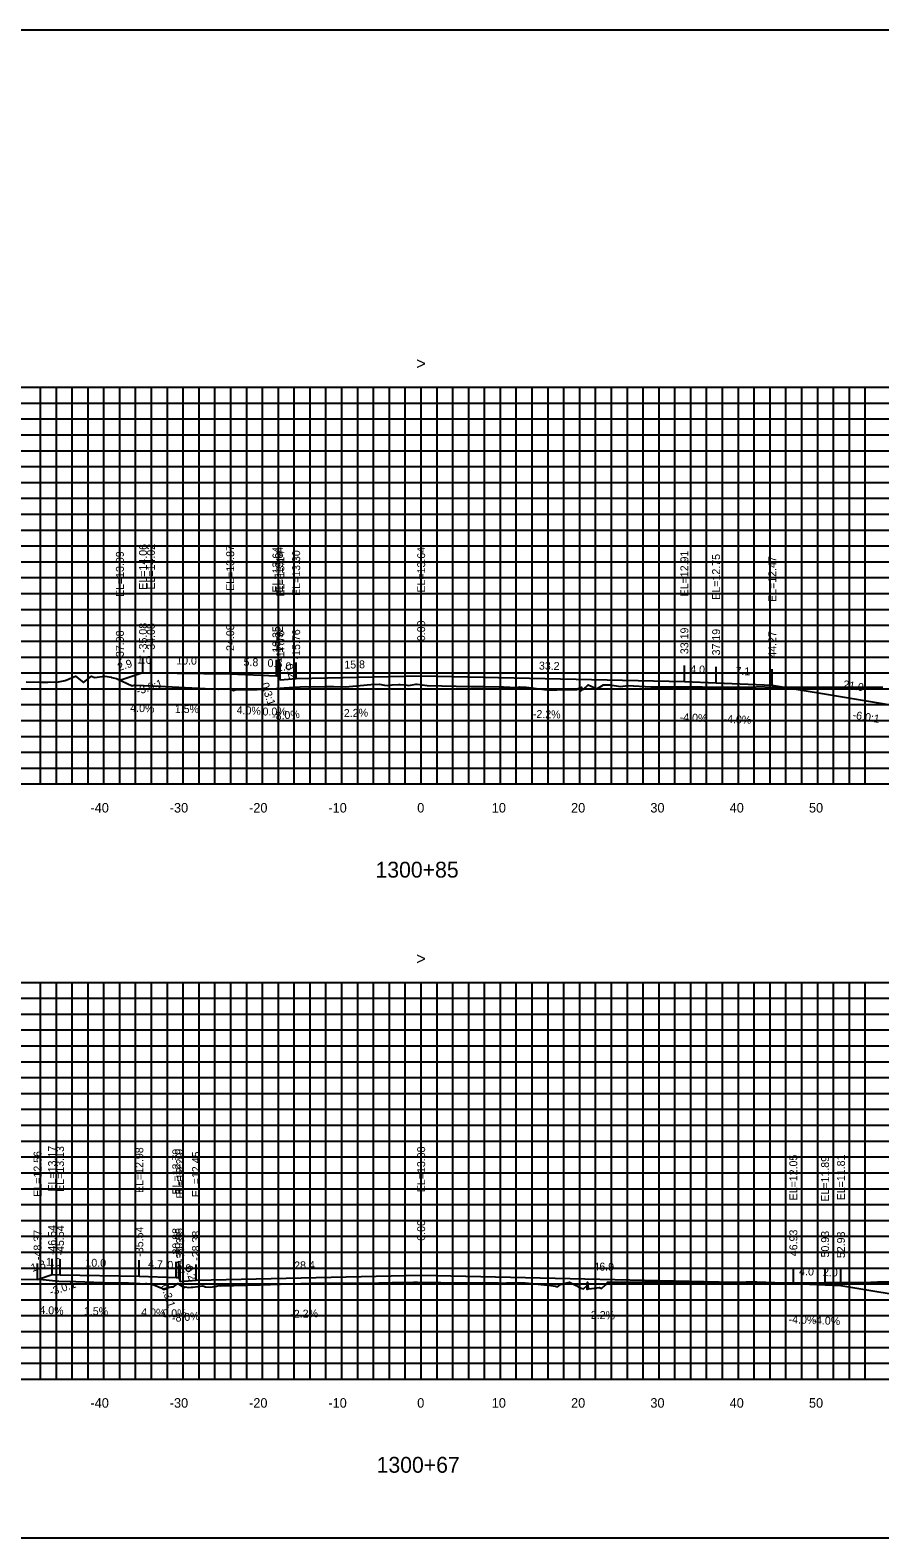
# Model space of a CAD drawing. Extents: x 1797714 to 1804825, y 249015 to 250269.
# Drawn here: x 1802214.9 to 1802322, y 249628.2 to 249818.2 of the extents above; entities that cross this region are included whole.
import ezdxf

# ---------------------------------------------------------------- set-up
doc = ezdxf.new("R2010")
doc.units = 0
for name, color, linetype in [('1', 7, 'Continuous'), ('10', 7, 'Continuous'), ('3', 7, 'Continuous'), ('4', 7, 'Continuous'), ('60', 7, 'Continuous'), ('CL-CNST', 7, 'Continuous'), ('Level 62', 7, 'Continuous'), ('M-ROADS', 7, 'Continuous')]:
    doc.layers.add(name, color=color, linetype=linetype)

msp = doc.modelspace()

# ---------------------------------------------------------------- linework, layer by layer
for p, q in [((1802226.17, 249736.26), (1802226.17, 249738.26)), ((1802229.08, 249737.23), (1802229.08, 249739.23)), ((1802230.08, 249737.19), (1802230.08, 249739.19)), ((1802240.08, 249737.04), (1802240.08, 249739.04)), ((1802245.91, 249736.8), (1802245.91, 249738.8)), ((1802246.24, 249736.8), (1802246.24, 249738.8)), ((1802246.4, 249736.3), (1802246.4, 249738.3)), ((1802248.4, 249736.46), (1802248.4, 249738.46)), ((1802264.16, 249736.81), (1802264.16, 249738.81)), ((1802297.35, 249736.08), (1802297.35, 249738.08)), ((1802301.35, 249735.92), (1802301.35, 249737.92)), ((1802308.43, 249735.64), (1802308.43, 249737.64)), ((1802215.79, 249660.73), (1802215.79, 249662.73)), ((1802217.62, 249661.34), (1802217.62, 249663.34)), ((1802218.62, 249661.3), (1802218.62, 249663.3)), ((1802228.62, 249661.15), (1802228.62, 249663.15)), ((1802233.28, 249660.96), (1802233.28, 249662.96)), ((1802233.61, 249660.96), (1802233.61, 249662.96)), ((1802233.77, 249660.46), (1802233.77, 249662.46)), ((1802235.77, 249660.62), (1802235.77, 249662.62)), ((1802264.16, 249661.25), (1802264.16, 249663.25)), ((1802311.09, 249660.21), (1802311.09, 249662.21)), ((1802315.09, 249660.05), (1802315.09, 249662.05)), ((1802317.09, 249659.97), (1802317.09, 249661.97))]:
    msp.add_line(p, q)
msp.add_lwpolyline([(1802114.16, 249628.17), (1802414.16, 249628.17), (1802414.16, 249818.17), (1802114.16, 249818.17)], close=True)
at = {"layer": '60'}
for p, q in [((1802114.16, 249723.17), (1802414.16, 249723.17)), ((1802224.16, 249723.11), (1802224.16, 249723.17)), ((1802234.16, 249723.11), (1802234.16, 249723.17)), ((1802244.16, 249723.11), (1802244.16, 249723.17)), ((1802254.16, 249723.11), (1802254.16, 249723.17)), ((1802264.16, 249723.11), (1802264.16, 249723.17)), ((1802274.16, 249723.11), (1802274.16, 249723.17)), ((1802284.16, 249723.11), (1802284.16, 249723.17)), ((1802294.16, 249723.11), (1802294.16, 249723.17)), ((1802304.16, 249723.11), (1802304.16, 249723.17)), ((1802314.16, 249723.11), (1802314.16, 249723.17)), ((1802114.16, 249648.17), (1802414.16, 249648.17)), ((1802224.16, 249648.11), (1802224.16, 249648.17)), ((1802234.16, 249648.11), (1802234.16, 249648.17)), ((1802244.16, 249648.11), (1802244.16, 249648.17)), ((1802254.16, 249648.11), (1802254.16, 249648.17)), ((1802264.16, 249648.11), (1802264.16, 249648.17)), ((1802274.16, 249648.11), (1802274.16, 249648.17)), ((1802284.16, 249648.11), (1802284.16, 249648.17)), ((1802294.16, 249648.11), (1802294.16, 249648.17)), ((1802304.16, 249648.11), (1802304.16, 249648.17)), ((1802314.16, 249648.11), (1802314.16, 249648.17))]:
    msp.add_line(p, q, dxfattribs=at)
at = {"layer": 'CL-CNST'}
for points in [[(1802226.17, 249736.26), (1802229.08, 249737.23), (1802230.08, 249737.19), (1802240.08, 249737.04), (1802245.91, 249736.8), (1802246.24, 249736.8), (1802246.4, 249736.3), (1802248.4, 249736.46), (1802264.16, 249736.81), (1802297.35, 249736.08), (1802301.35, 249735.92), (1802308.43, 249735.64), (1802329.43, 249732.14), (1802333.43, 249732.14), (1802345.04, 249735.04)], [(1802215.79, 249660.73), (1802217.62, 249661.34), (1802218.62, 249661.3), (1802228.62, 249661.15), (1802233.28, 249660.96), (1802233.61, 249660.96), (1802233.77, 249660.46), (1802235.77, 249660.62), (1802264.16, 249661.25), (1802311.09, 249660.21), (1802315.09, 249660.05), (1802317.09, 249659.97), (1802338.09, 249656.47), (1802342.09, 249656.47), (1802355.26, 249659.77)]]:
    msp.add_lwpolyline(points, dxfattribs=at)
at = {"layer": 'Level 62'}
for p, q in [((1802114.16, 249773.17), (1802414.16, 249773.17)), ((1802216.16, 249723.17), (1802216.16, 249773.17)), ((1802218.16, 249723.17), (1802218.16, 249773.17)), ((1802220.16, 249723.17), (1802220.16, 249773.17)), ((1802222.16, 249723.17), (1802222.16, 249773.17)), ((1802224.16, 249723.17), (1802224.16, 249773.17)), ((1802226.16, 249723.17), (1802226.16, 249773.17)), ((1802228.16, 249723.17), (1802228.16, 249773.17)), ((1802230.16, 249723.17), (1802230.16, 249773.17)), ((1802232.16, 249723.17), (1802232.16, 249773.17)), ((1802234.16, 249723.17), (1802234.16, 249773.17)), ((1802236.16, 249723.17), (1802236.16, 249773.17)), ((1802238.16, 249723.17), (1802238.16, 249773.17)), ((1802240.16, 249723.17), (1802240.16, 249773.17)), ((1802242.16, 249723.17), (1802242.16, 249773.17)), ((1802244.16, 249723.17), (1802244.16, 249773.17)), ((1802246.16, 249723.17), (1802246.16, 249773.17)), ((1802248.16, 249723.17), (1802248.16, 249773.17)), ((1802250.16, 249723.17), (1802250.16, 249773.17)), ((1802252.16, 249723.17), (1802252.16, 249773.17)), ((1802254.16, 249723.17), (1802254.16, 249773.17)), ((1802256.16, 249723.17), (1802256.16, 249773.17)), ((1802258.16, 249723.17), (1802258.16, 249773.17)), ((1802260.16, 249723.17), (1802260.16, 249773.17)), ((1802262.16, 249723.17), (1802262.16, 249773.17)), ((1802264.16, 249723.17), (1802264.16, 249773.17)), ((1802266.16, 249723.17), (1802266.16, 249773.17)), ((1802268.16, 249723.17), (1802268.16, 249773.17)), ((1802270.16, 249723.17), (1802270.16, 249773.17)), ((1802272.16, 249723.17), (1802272.16, 249773.17)), ((1802274.16, 249723.17), (1802274.16, 249773.17)), ((1802276.16, 249723.17), (1802276.16, 249773.17)), ((1802278.16, 249723.17), (1802278.16, 249773.17)), ((1802280.16, 249723.17), (1802280.16, 249773.17)), ((1802282.16, 249723.17), (1802282.16, 249773.17)), ((1802284.16, 249723.17), (1802284.16, 249773.17)), ((1802286.16, 249723.17), (1802286.16, 249773.17)), ((1802288.16, 249723.17), (1802288.16, 249773.17)), ((1802290.16, 249723.17), (1802290.16, 249773.17)), ((1802292.16, 249723.17), (1802292.16, 249773.17)), ((1802294.16, 249723.17), (1802294.16, 249773.17)), ((1802296.16, 249723.17), (1802296.16, 249773.17)), ((1802298.16, 249723.17), (1802298.16, 249773.17)), ((1802300.16, 249723.17), (1802300.16, 249773.17)), ((1802302.16, 249723.17), (1802302.16, 249773.17)), ((1802304.16, 249723.17), (1802304.16, 249773.17)), ((1802306.16, 249723.17), (1802306.16, 249773.17)), ((1802308.16, 249723.17), (1802308.16, 249773.17)), ((1802310.16, 249723.17), (1802310.16, 249773.17)), ((1802312.16, 249723.17), (1802312.16, 249773.17)), ((1802314.16, 249723.17), (1802314.16, 249773.17)), ((1802316.16, 249723.17), (1802316.16, 249773.17)), ((1802318.16, 249723.17), (1802318.16, 249773.17)), ((1802320.16, 249723.17), (1802320.16, 249773.17)), ((1802114.16, 249771.17), (1802414.16, 249771.17)), ((1802114.16, 249769.17), (1802414.16, 249769.17)), ((1802114.16, 249767.17), (1802414.16, 249767.17)), ((1802114.16, 249765.17), (1802414.16, 249765.17)), ((1802114.16, 249763.17), (1802414.16, 249763.17)), ((1802114.16, 249761.17), (1802414.16, 249761.17)), ((1802114.16, 249759.17), (1802414.16, 249759.17)), ((1802114.16, 249757.17), (1802414.16, 249757.17)), ((1802114.16, 249755.17), (1802414.16, 249755.17)), ((1802114.16, 249753.17), (1802414.16, 249753.17)), ((1802114.16, 249751.17), (1802414.16, 249751.17)), ((1802114.16, 249749.17), (1802414.16, 249749.17)), ((1802114.16, 249747.17), (1802414.16, 249747.17)), ((1802114.16, 249745.17), (1802414.16, 249745.17)), ((1802114.16, 249743.17), (1802414.16, 249743.17)), ((1802114.16, 249741.17), (1802414.16, 249741.17)), ((1802114.16, 249739.17), (1802414.16, 249739.17)), ((1802114.16, 249737.17), (1802414.16, 249737.17)), ((1802114.16, 249735.17), (1802414.16, 249735.17)), ((1802114.16, 249733.17), (1802414.16, 249733.17)), ((1802114.16, 249731.17), (1802414.16, 249731.17)), ((1802114.16, 249729.17), (1802414.16, 249729.17)), ((1802114.16, 249727.17), (1802414.16, 249727.17)), ((1802114.16, 249725.17), (1802414.16, 249725.17)), ((1802114.16, 249723.17), (1802414.16, 249723.17)), ((1802114.16, 249698.17), (1802414.16, 249698.17)), ((1802216.16, 249648.17), (1802216.16, 249698.17)), ((1802218.16, 249648.17), (1802218.16, 249698.17)), ((1802220.16, 249648.17), (1802220.16, 249698.17)), ((1802222.16, 249648.17), (1802222.16, 249698.17)), ((1802224.16, 249648.17), (1802224.16, 249698.17)), ((1802226.16, 249648.17), (1802226.16, 249698.17)), ((1802228.16, 249648.17), (1802228.16, 249698.17)), ((1802230.16, 249648.17), (1802230.16, 249698.17)), ((1802232.16, 249648.17), (1802232.16, 249698.17)), ((1802234.16, 249648.17), (1802234.16, 249698.17)), ((1802236.16, 249648.17), (1802236.16, 249698.17)), ((1802238.16, 249648.17), (1802238.16, 249698.17)), ((1802240.16, 249648.17), (1802240.16, 249698.17)), ((1802242.16, 249648.17), (1802242.16, 249698.17)), ((1802244.16, 249648.17), (1802244.16, 249698.17)), ((1802246.16, 249648.17), (1802246.16, 249698.17)), ((1802248.16, 249648.17), (1802248.16, 249698.17)), ((1802250.16, 249648.17), (1802250.16, 249698.17)), ((1802252.16, 249648.17), (1802252.16, 249698.17)), ((1802254.16, 249648.17), (1802254.16, 249698.17)), ((1802256.16, 249648.17), (1802256.16, 249698.17)), ((1802258.16, 249648.17), (1802258.16, 249698.17)), ((1802260.16, 249648.17), (1802260.16, 249698.17)), ((1802262.16, 249648.17), (1802262.16, 249698.17)), ((1802264.16, 249648.17), (1802264.16, 249698.17)), ((1802266.16, 249648.17), (1802266.16, 249698.17)), ((1802268.16, 249648.17), (1802268.16, 249698.17)), ((1802270.16, 249648.17), (1802270.16, 249698.17)), ((1802272.16, 249648.17), (1802272.16, 249698.17)), ((1802274.16, 249648.17), (1802274.16, 249698.17)), ((1802276.16, 249648.17), (1802276.16, 249698.17)), ((1802278.16, 249648.17), (1802278.16, 249698.17)), ((1802280.16, 249648.17), (1802280.16, 249698.17)), ((1802282.16, 249648.17), (1802282.16, 249698.17)), ((1802284.16, 249648.17), (1802284.16, 249698.17)), ((1802286.16, 249648.17), (1802286.16, 249698.17)), ((1802288.16, 249648.17), (1802288.16, 249698.17)), ((1802290.16, 249648.17), (1802290.16, 249698.17)), ((1802292.16, 249648.17), (1802292.16, 249698.17)), ((1802294.16, 249648.17), (1802294.16, 249698.17)), ((1802296.16, 249648.17), (1802296.16, 249698.17)), ((1802298.16, 249648.17), (1802298.16, 249698.17)), ((1802300.16, 249648.17), (1802300.16, 249698.17)), ((1802302.16, 249648.17), (1802302.16, 249698.17)), ((1802304.16, 249648.17), (1802304.16, 249698.17)), ((1802306.16, 249648.17), (1802306.16, 249698.17)), ((1802308.16, 249648.17), (1802308.16, 249698.17)), ((1802310.16, 249648.17), (1802310.16, 249698.17)), ((1802312.16, 249648.17), (1802312.16, 249698.17)), ((1802314.16, 249648.17), (1802314.16, 249698.17)), ((1802316.16, 249648.17), (1802316.16, 249698.17)), ((1802318.16, 249648.17), (1802318.16, 249698.17)), ((1802320.16, 249648.17), (1802320.16, 249698.17)), ((1802114.16, 249696.17), (1802414.16, 249696.17)), ((1802114.16, 249694.17), (1802414.16, 249694.17)), ((1802114.16, 249692.17), (1802414.16, 249692.17)), ((1802114.16, 249690.17), (1802414.16, 249690.17)), ((1802114.16, 249688.17), (1802414.16, 249688.17)), ((1802114.16, 249686.17), (1802414.16, 249686.17)), ((1802114.16, 249684.17), (1802414.16, 249684.17)), ((1802114.16, 249682.17), (1802414.16, 249682.17)), ((1802114.16, 249680.17), (1802414.16, 249680.17)), ((1802114.16, 249678.17), (1802414.16, 249678.17)), ((1802114.16, 249676.17), (1802414.16, 249676.17)), ((1802114.16, 249674.17), (1802414.16, 249674.17)), ((1802114.16, 249672.17), (1802414.16, 249672.17)), ((1802114.16, 249670.17), (1802414.16, 249670.17)), ((1802114.16, 249668.17), (1802414.16, 249668.17)), ((1802114.16, 249666.17), (1802414.16, 249666.17)), ((1802114.16, 249664.17), (1802414.16, 249664.17)), ((1802114.16, 249662.17), (1802414.16, 249662.17)), ((1802114.16, 249660.17), (1802414.16, 249660.17)), ((1802114.16, 249658.17), (1802414.16, 249658.17)), ((1802114.16, 249656.17), (1802414.16, 249656.17)), ((1802114.16, 249654.17), (1802414.16, 249654.17)), ((1802114.16, 249652.17), (1802414.16, 249652.17)), ((1802114.16, 249650.17), (1802414.16, 249650.17)), ((1802114.16, 249648.17), (1802414.16, 249648.17))]:
    msp.add_line(p, q, dxfattribs=at)
at = {"layer": 'M-ROADS'}
for points in [[(1802214.35, 249736.06), (1802216.33, 249736.01), (1802216.52, 249736.01), (1802217.1, 249736), (1802218.41, 249736.03), (1802219.29, 249736.23), (1802220.59, 249736.76), (1802221.59, 249735.97), (1802222.59, 249736.76), (1802222.96, 249736.57), (1802224.29, 249736.76), (1802225.1, 249736.65), (1802225.12, 249736.59), (1802225.75, 249736.46), (1802227.73, 249735.54), (1802227.8, 249735.59), (1802227.97, 249735.62), (1802227.98, 249735.63), (1802227.99, 249735.62), (1802228.04, 249735.62), (1802230.25, 249735.54), (1802230.26, 249735.54), (1802230.26, 249735.54), (1802230.27, 249735.54), (1802230.28, 249735.54), (1802238.57, 249735.12), (1802238.59, 249735.12), (1802239.88, 249735.22), (1802240.18, 249735.18), (1802240.48, 249734.94), (1802240.57, 249734.98), (1802240.95, 249735.08), (1802241.02, 249735.09), (1802241.19, 249735.09), (1802241.84, 249735.07), (1802242.64, 249735.06), (1802243.46, 249735.07), (1802243.98, 249735.11), (1802244.39, 249735.08), (1802246.89, 249735.27), (1802247.53, 249735.33), (1802249.62, 249735.44), (1802250.01, 249735.43), (1802250.65, 249735.44), (1802252.08, 249735.43), (1802252.22, 249735.46), (1802253.15, 249735.47), (1802254.6, 249735.43), (1802256.47, 249735.59), (1802257.8, 249735.71), (1802258.91, 249735.73), (1802259.54, 249735.64), (1802259.94, 249735.58), (1802260.51, 249735.68), (1802261.31, 249735.72), (1802261.51, 249735.71), (1802262.16, 249735.67), (1802262.62, 249735.6), (1802263.48, 249735.75), (1802263.53, 249735.76), (1802263.55, 249735.76), (1802263.66, 249735.75), (1802264.91, 249735.56), (1802270.43, 249735.46), (1802271.62, 249735.44), (1802272.04, 249735.44), (1802274.01, 249735.43), (1802274.33, 249735.42), (1802274.36, 249735.41), (1802274.45, 249735.41), (1802274.54, 249735.41), (1802276.12, 249735.32), (1802276.59, 249735.41), (1802277.4, 249735.37), (1802280.05, 249735.05), (1802281.25, 249735.03), (1802283.07, 249735.08), (1802283.63, 249735.09), (1802283.82, 249735.06), (1802283.87, 249735.17), (1802284.03, 249735.23), (1802284.13, 249735.12), (1802284.26, 249734.92), (1802284.32, 249734.93), (1802284.33, 249734.93), (1802284.34, 249734.96), (1802284.37, 249735.39), (1802284.42, 249735.04), (1802284.57, 249735.08), (1802284.87, 249735.32), (1802285.22, 249735.66), (1802285.96, 249735.32), (1802286.3, 249735.17), (1802286.32, 249735.17), (1802287.14, 249735.68), (1802288, 249735.68), (1802289.29, 249735.44), (1802290.23, 249735.56), (1802293.11, 249735.41), (1802293.58, 249735.41), (1802293.71, 249735.41), (1802294.35, 249735.41), (1802299.6, 249735.42), (1802304.56, 249735.38), (1802305.24, 249735.38), (1802305.31, 249735.38), (1802305.35, 249735.38), (1802305.67, 249735.38), (1802307.14, 249735.44), (1802307.77, 249735.38), (1802308.22, 249735.38), (1802309.74, 249735.38), (1802311.11, 249735.38), (1802321.47, 249735.35), (1802322.38, 249735.35)], [(1802212.33, 249660.77), (1802216.44, 249660.72), (1802218.49, 249660.53), (1802220.61, 249660.46), (1802224.04, 249660.33), (1802227.27, 249660.29), (1802228.67, 249660.24), (1802229.39, 249660.19), (1802229.45, 249660.2), (1802229.58, 249660.2), (1802230.22, 249660.15), (1802231.67, 249659.56), (1802232.62, 249659.78), (1802232.95, 249659.81), (1802233.49, 249660.2), (1802234.15, 249659.82), (1802234.31, 249659.72), (1802234.31, 249659.76), (1802234.34, 249659.8), (1802234.81, 249659.71), (1802235.16, 249659.75), (1802235.36, 249659.76), (1802236.63, 249659.93), (1802236.97, 249659.81), (1802237.61, 249659.75), (1802238.37, 249659.9), (1802238.65, 249659.96), (1802238.69, 249659.96), (1802238.85, 249659.92), (1802242.27, 249660.02), (1802243.87, 249660.06), (1802250.31, 249660.27), (1802250.47, 249660.26), (1802252.72, 249660.26), (1802253.02, 249660.27), (1802253.22, 249660.27), (1802255.29, 249660.25), (1802256.57, 249660.27), (1802256.69, 249660.27), (1802257.13, 249660.28), (1802260.52, 249660.34), (1802261.2, 249660.33), (1802262.89, 249660.33), (1802263.17, 249660.36), (1802263.25, 249660.37), (1802263.71, 249660.37), (1802265.5, 249660.34), (1802266.66, 249660.35), (1802270.51, 249660.31), (1802272.29, 249660.3), (1802272.92, 249660.29), (1802273.9, 249660.32), (1802274.66, 249660.28), (1802274.94, 249660.3), (1802275, 249660.31), (1802275.42, 249660.31), (1802277.26, 249660.3), (1802280.53, 249659.96), (1802281.1, 249659.9), (1802281.34, 249659.81), (1802281.74, 249660.09), (1802282.86, 249660.39), (1802283.69, 249659.97), (1802283.83, 249659.91), (1802283.88, 249659.9), (1802284.29, 249659.65), (1802284.33, 249659.63), (1802284.33, 249659.63), (1802284.34, 249659.63), (1802284.35, 249659.62), (1802284.65, 249659.56), (1802284.67, 249659.61), (1802285.03, 249659.93), (1802285.08, 249659.45), (1802285.08, 249660.08), (1802285.1, 249660.21), (1802285.15, 249660.38), (1802285.21, 249659.64), (1802285.24, 249659.54), (1802285.24, 249659.53), (1802285.3, 249659.53), (1802286.64, 249659.7), (1802286.91, 249659.61), (1802287.42, 249660.06), (1802287.65, 249660.39), (1802288.57, 249660.39), (1802289.02, 249660.4), (1802289.05, 249660.37), (1802289.07, 249660.39), (1802289.08, 249660.4), (1802289.08, 249660.4), (1802289.1, 249660.34), (1802289.24, 249660.4), (1802289.74, 249660.4), (1802292.24, 249660.39), (1802301.46, 249660.43), (1802302.02, 249660.35), (1802303.61, 249660.38), (1802305.15, 249660.42), (1802305.93, 249660.43), (1802306.49, 249660.44), (1802308.74, 249660.36), (1802309.29, 249660.3), (1802309.3, 249660.31), (1802309.39, 249660.31), (1802309.77, 249660.3), (1802315.05, 249660.35), (1802320.02, 249660.35), (1802321.69, 249660.45), (1802323.18, 249660.45)]]:
    msp.add_lwpolyline(points, dxfattribs=at)

# ---------------------------------------------------------------- texts
for s, rotation, p in [('-3.0:1', 18.4349, (1802228.42, 249734.37)), ('0.3:1', 288.4353, (1802243.95, 249735.76)), ('-6.0:1', 350.5377, (1802318.51, 249731.42)), ('-3.0:1', 18.4349, (1802217.49, 249658.66)), ('0.3:1', 288.4353, (1802231.32, 249659.92))]:
    msp.add_text(s, height=1, rotation=rotation).set_placement(p)
at = {"layer": '1'}
for s, p in [('1300+85', (1802258.4, 249711.37)), ('1300+67', (1802258.54, 249636.37))]:
    msp.add_text(s, height=2, dxfattribs=at).set_placement(p)
at = {"layer": '10'}
for s, p in [('-40', (1802222.46, 249719.57)), ('-30', (1802232.46, 249719.57)), ('-20', (1802242.46, 249719.57)), ('-10', (1802252.46, 249719.57)), ('0', (1802263.66, 249719.57)), ('10', (1802273.06, 249719.57)), ('20', (1802283.06, 249719.57)), ('30', (1802293.06, 249719.57)), ('40', (1802303.06, 249719.57)), ('50', (1802313.06, 249719.57)), ('-40', (1802222.46, 249644.57)), ('-30', (1802232.46, 249644.57)), ('-20', (1802242.46, 249644.57)), ('-10', (1802252.46, 249644.57)), ('0', (1802263.66, 249644.57)), ('10', (1802273.06, 249644.57)), ('20', (1802283.06, 249644.57)), ('30', (1802293.06, 249644.57)), ('40', (1802303.06, 249644.57)), ('50', (1802313.06, 249644.57))]:
    msp.add_text(s, height=1.2, dxfattribs=at).set_placement(p)
at = {"layer": '3'}
for s, p in [('EL=14.06', (1802229.58, 249747.65)), ('EL=14.02', (1802230.58, 249747.66)), ('EL=13.87', (1802240.58, 249747.51)), ('EL=13.09', (1802226.67, 249746.73)), ('EL=13.64', (1802246.41, 249747.28)), ('EL=13.64', (1802246.74, 249747.28)), ('EL=13.14', (1802246.9, 249746.78)), ('EL=13.30', (1802248.9, 249746.86)), ('EL=13.64', (1802264.66, 249747.28)), ('EL=12.91', (1802297.85, 249746.81)), ('EL=12.75', (1802301.85, 249746.39)), ('EL=12.47', (1802308.93, 249746.11)), ('0.00', (1802264.66, 249741.17)), ('-37.98', (1802226.67, 249738.72)), ('-35.08', (1802229.58, 249739.68)), ('-34.08', (1802230.58, 249739.64)), ('-24.08', (1802240.58, 249739.49)), ('-18.25', (1802246.41, 249739.26)), ('-17.92', (1802246.74, 249739.26)), ('-17.76', (1802246.9, 249738.71)), ('-15.76', (1802248.9, 249738.87)), ('33.19', (1802297.85, 249739.53)), ('37.19', (1802301.85, 249739.37)), ('44.27', (1802308.93, 249739.09)), ('EL=13.17', (1802218.12, 249671.81)), ('EL=13.13', (1802219.12, 249671.77)), ('EL=12.98', (1802229.12, 249671.62)), ('EL=12.79', (1802233.78, 249671.43)), ('EL=12.79', (1802234.11, 249671.43)), ('EL=13.08', (1802264.66, 249671.72)), ('EL=12.56', (1802216.29, 249671.15)), ('EL=12.29', (1802234.27, 249670.93)), ('EL=12.45', (1802236.27, 249671.09)), ('EL=12.05', (1802311.59, 249670.69)), ('EL=11.89', (1802315.59, 249670.53)), ('EL=11.81', (1802317.59, 249670.7)), ('0.00', (1802264.66, 249665.61)), ('-48.37', (1802216.29, 249663.18)), ('-46.54', (1802218.12, 249663.79)), ('-45.54', (1802219.12, 249663.75)), ('-35.54', (1802229.12, 249663.6)), ('-30.88', (1802233.78, 249663.42)), ('-30.55', (1802234.11, 249663.42)), ('-30.38', (1802234.27, 249662.92)), ('-28.38', (1802236.27, 249663.08)), ('46.93', (1802311.59, 249663.66)), ('50.93', (1802315.59, 249663.5)), ('52.93', (1802317.59, 249663.42))]:
    msp.add_text(s, height=1, rotation=90, dxfattribs=at).set_placement(p)
at = {"layer": '4'}
for s, rotation, p in [('2.9', 18.4349, (1802226.06, 249737.38)), ('1.0', 357.7094, (1802228.3, 249738.36)), ('10.0', 359.1406, (1802233.27, 249738.24)), ('5.8', 357.7094, (1802241.75, 249738.07)), ('2.0', 4.5739, (1802246, 249737.38)), ('0.2', 288.4353, (1802246.96, 249738.12)), ('15.8', 1.2603, (1802254.48, 249737.7)), ('33.2', 358.7397, (1802279, 249737.59)), ('4.0', 357.7094, (1802298.07, 249737.15)), ('7.1', 357.7094, (1802303.78, 249736.93)), ('21.0', 350.5377, (1802317.31, 249735.27)), ('4.0%', 357.7094, (1802227.46, 249732.29)), ('1.5%', 359.1406, (1802233.09, 249732.14)), ('4.0%', 357.7094, (1802240.88, 249732)), ('-8.0%', 4.5739, (1802245.4, 249731.21)), ('-2.2%', 1.2603, (1802253.98, 249731.59)), ('-2.2%', 358.7397, (1802278.24, 249731.5)), ('-4.0%', 357.7094, (1802296.74, 249731.1)), ('-4.0%', 357.7094, (1802302.28, 249730.88)), ('1.8', 18.4349, (1802215.14, 249661.67)), ('1.0', 357.7094, (1802216.84, 249662.47)), ('10.0', 359.1406, (1802221.82, 249662.35)), ('4.7', 357.7094, (1802229.71, 249662.2)), ('2.0', 4.5739, (1802233.37, 249661.53)), ('0.2', 288.4353, (1802234.33, 249662.28)), ('28.4', 1.2603, (1802248.16, 249661.99)), ('46.9', 358.7397, (1802285.87, 249661.87)), ('4.0', 357.7094, (1802311.81, 249661.29)), ('2.0', 357.7094, (1802314.81, 249661.17)), ('4.0%', 357.7094, (1802216.01, 249656.4)), ('1.5%', 359.1406, (1802221.63, 249656.25)), ('4.0%', 357.7094, (1802228.84, 249656.13)), ('-8.0%', 4.5739, (1802232.77, 249655.36)), ('-2.2%', 1.2603, (1802247.67, 249655.88)), ('-2.2%', 358.7397, (1802285.1, 249655.78)), ('-4.0%', 357.7094, (1802310.48, 249655.23)), ('-4.0%', 357.7094, (1802313.48, 249655.11))]:
    msp.add_text(s, height=1, rotation=rotation, dxfattribs=at).set_placement(p)
for s, p in [('0.3', (1802244.79, 249737.9)), ('0.0%', (1802244.16, 249731.8)), ('0.3', (1802232.16, 249662.06)), ('0.0%', (1802231.53, 249655.96))]:
    msp.add_text(s, height=1, dxfattribs=at).set_placement(p)
at = {"layer": '60'}
for p in [(1802263.55, 249775.42), (1802263.55, 249700.42)]:
    msp.add_text('>', height=1.5, dxfattribs=at).set_placement(p)

doc.saveas('drawing.dxf')
